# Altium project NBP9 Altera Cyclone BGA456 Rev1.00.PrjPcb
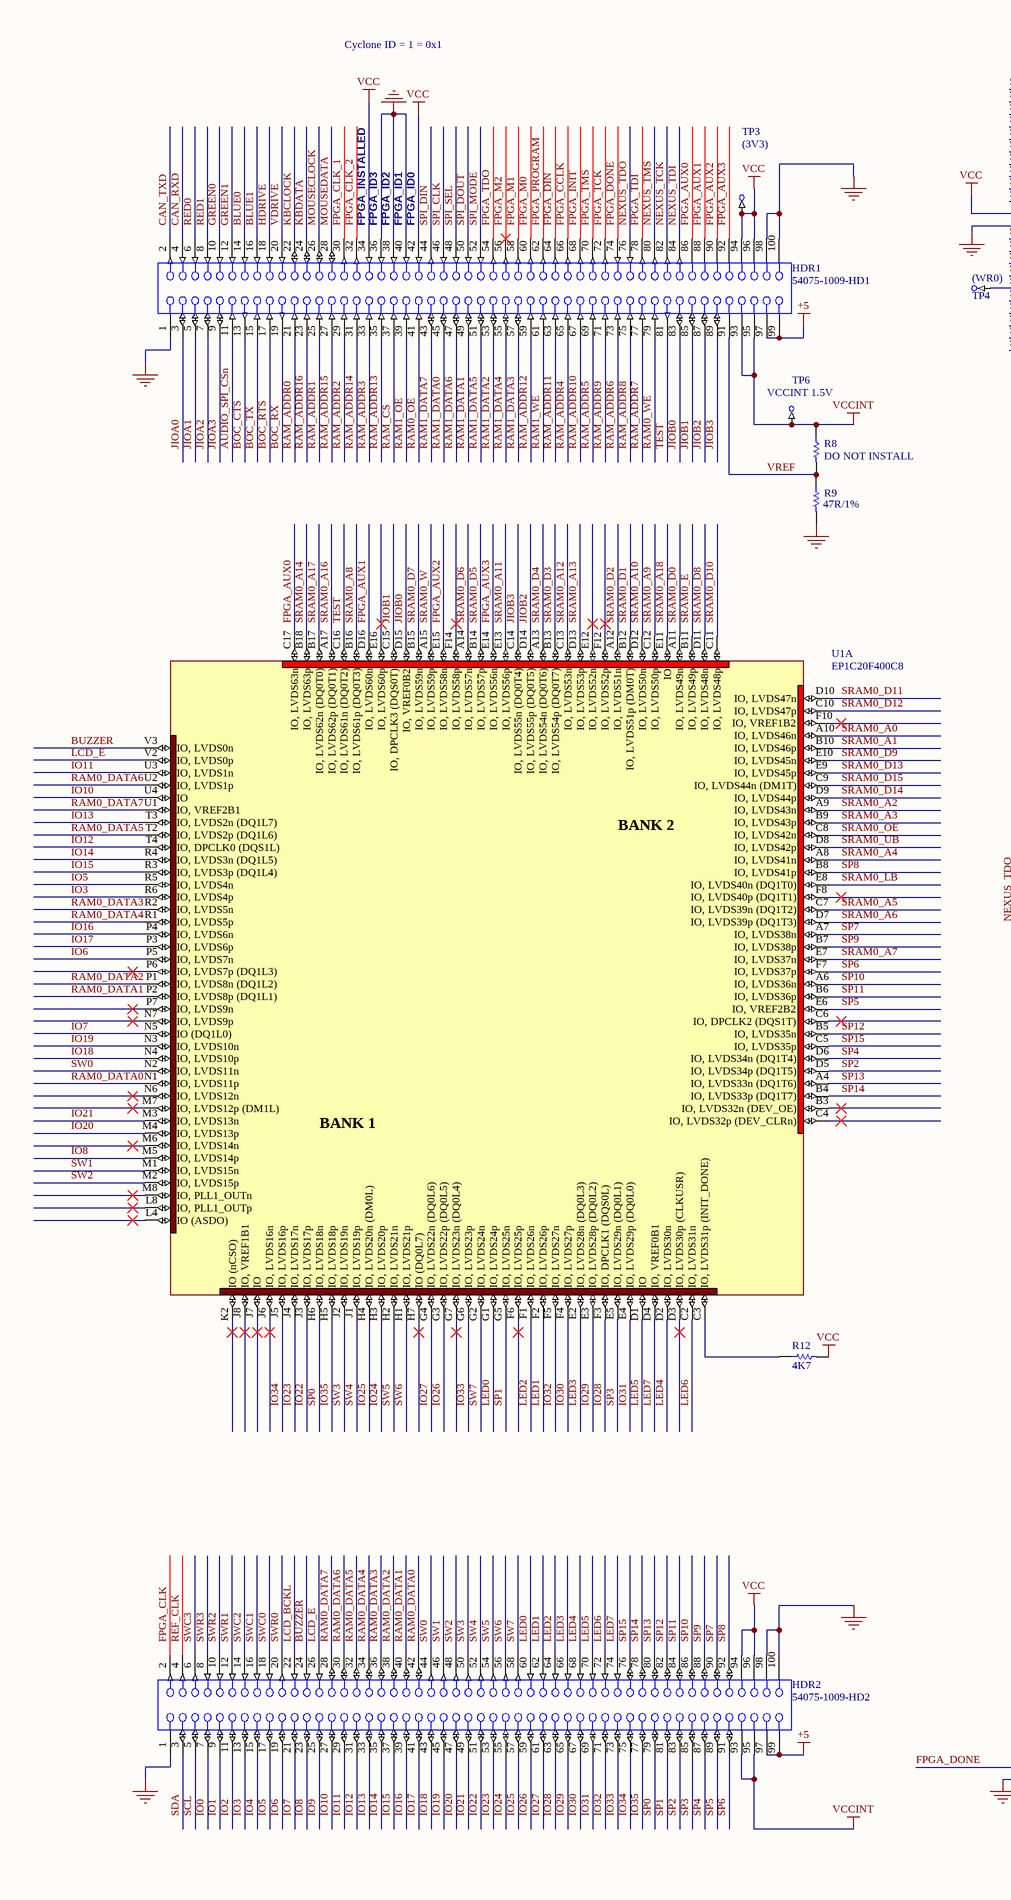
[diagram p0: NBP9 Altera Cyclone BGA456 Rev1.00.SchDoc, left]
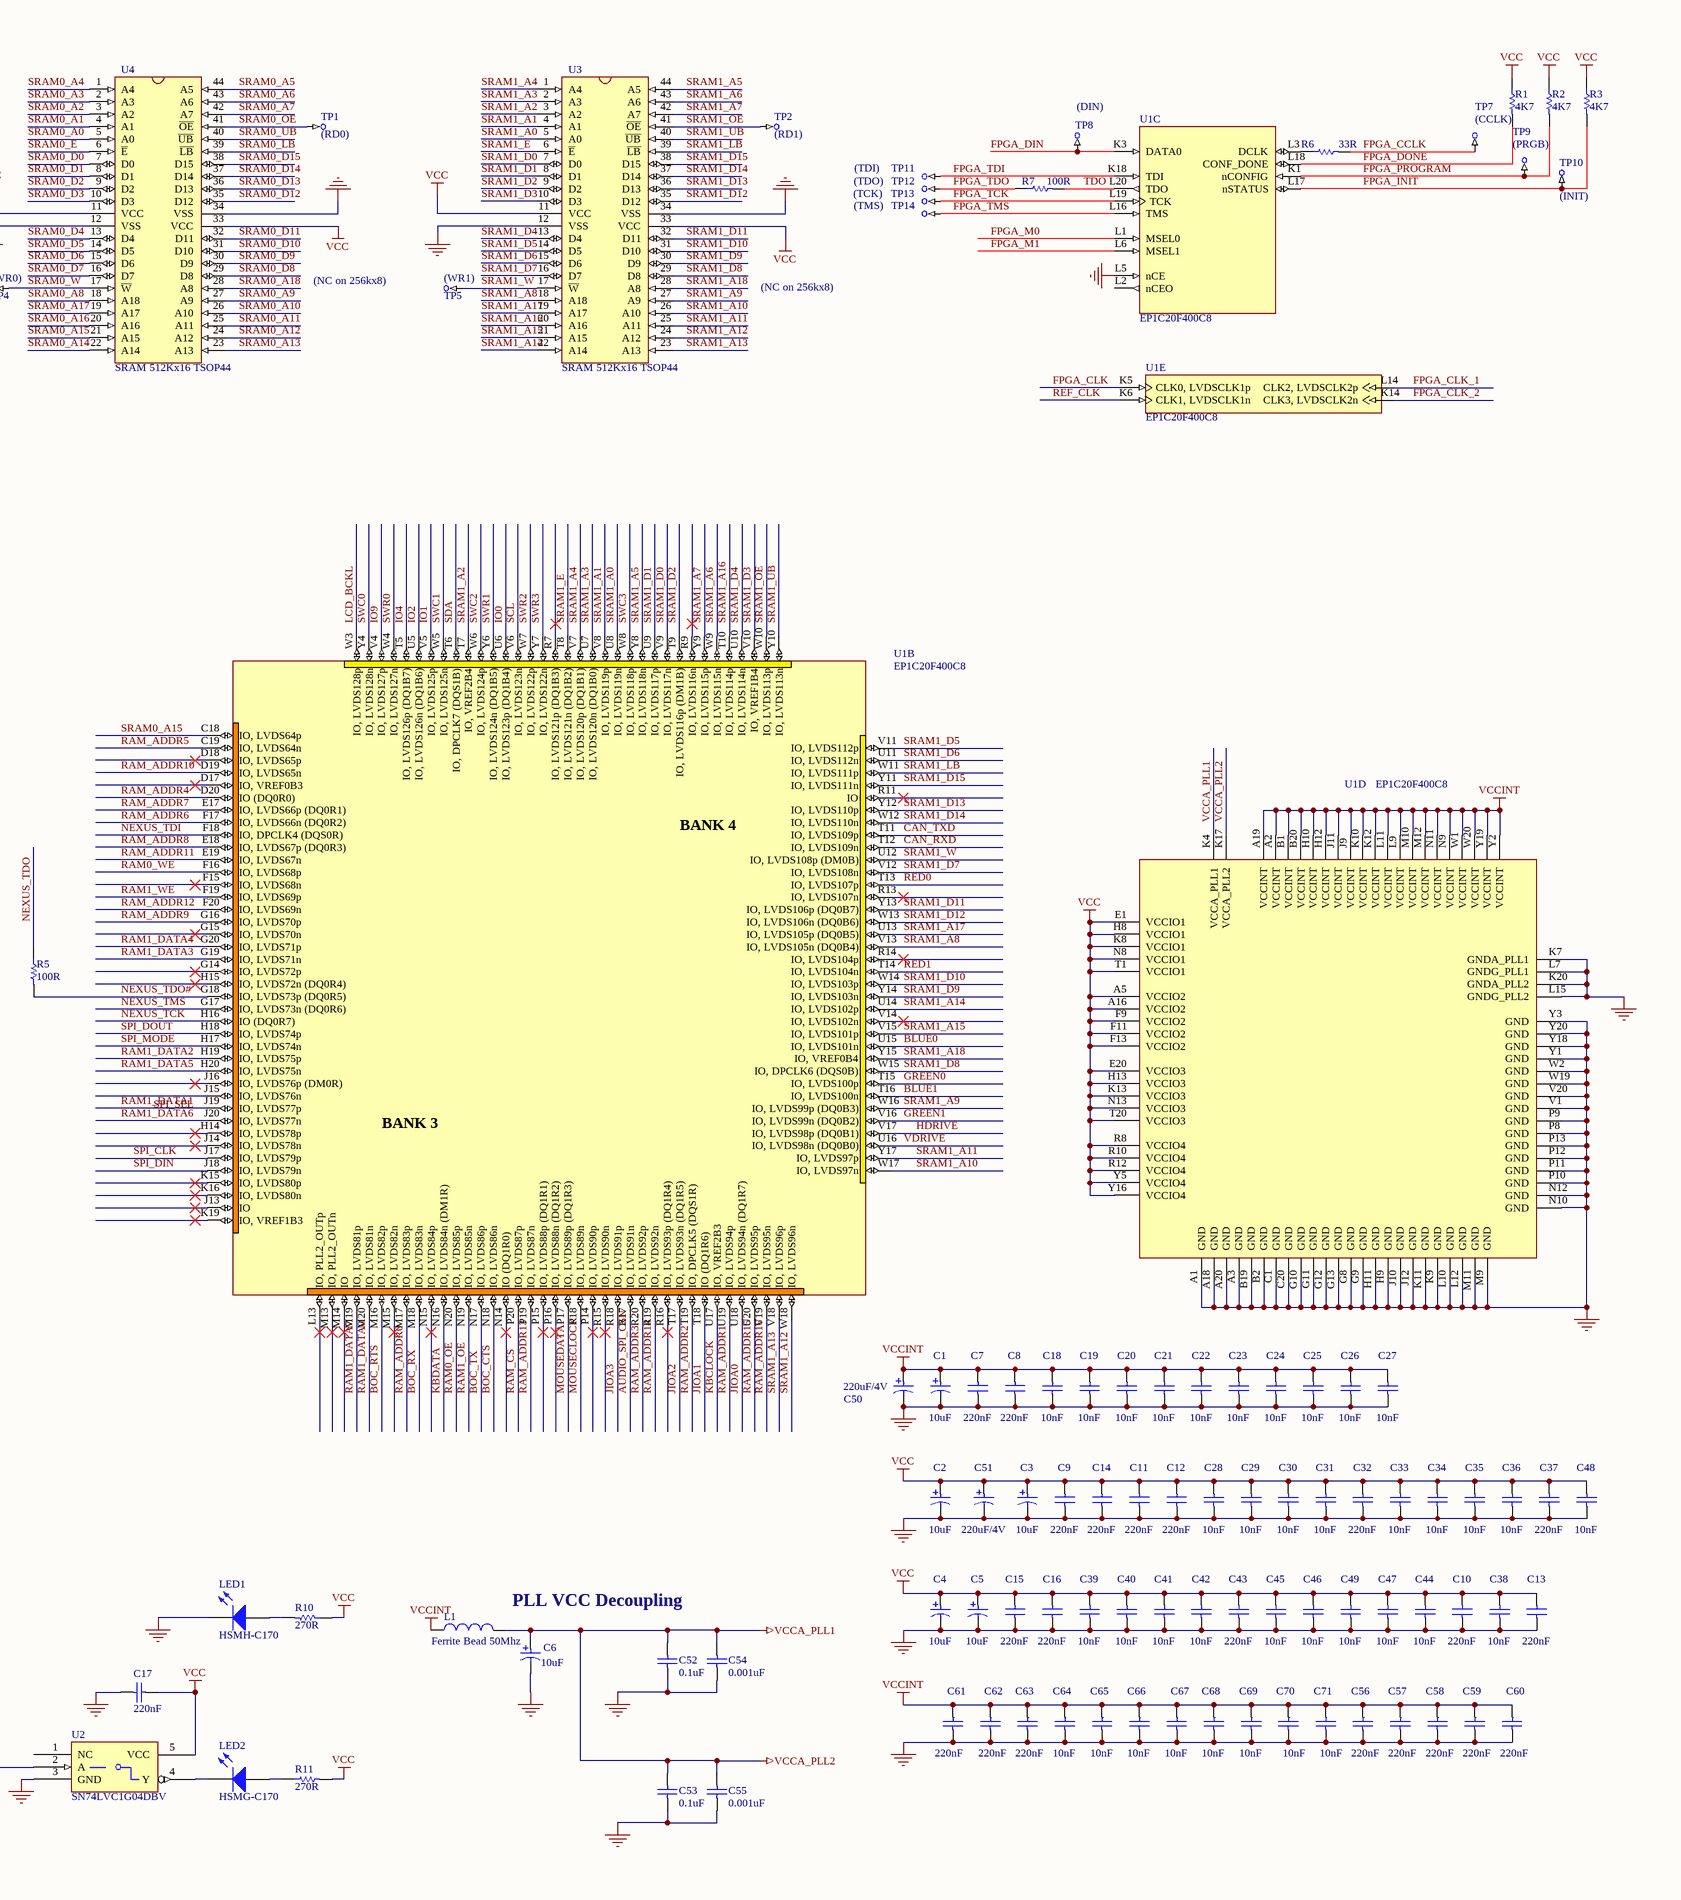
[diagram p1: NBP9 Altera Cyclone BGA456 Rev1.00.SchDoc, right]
1 sheet, 105 parts. Net scope: global (net labels, ports and power ports of the same name join across sheets).
Board file: NBP9 Altera Cyclone BGA456 Rev1.00.PcbDoc

## Sheet NBP9 Altera Cyclone BGA456 Rev1.00.SchDoc: Cyclone BGA400 Daughterboard
size A2; Author: Ch.W.; Organization: Altium Limited; Address1: L3, 12a Rodborough Rd; Address2: Frenchs Forest; Address3: NSW; Address4: Australia 2086; DocumentNumber: 1; Revision: 1.00; SheetNumber: 1; SheetTotal: 1

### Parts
C1  10uF  [MCCT-B]
C2  10uF  [MCCT-B]
C3  10uF  [MCCT-B]
C4  10uF  [MCCT-B]
C5  10uF  [MCCT-B]
C6  10uF  [MCCT-B]
C7  220nF  [CC1005-0402]
C8  220nF  [CC1005-0402]
C9  220nF  [CC1608-0603]
C10  220nF  [CC1005-0402]
C11  220nF  [CC1608-0603]
C12  220nF  [CC1608-0603]
C13  220nF  [CC1005-0402]
C14  220nF  [CC1608-0603]
C15  220nF  [CC1608-0603]
C16  220nF  [CC1608-0603]
C17  220nF  [CC1608-0603]
C18  10nF  [CC1005-0402]
C19  10nF  [CC1005-0402]
C20  10nF  [CC1005-0402]
C21  10nF  [CC1005-0402]
C22  10nF  [CC1005-0402]
C23  10nF  [CC1005-0402]
C24  10nF  [CC1005-0402]
C25  10nF  [CC1005-0402]
C26  10nF  [CC1005-0402]
C27  10nF  [CC1005-0402]
C28  10nF  [CC1608-0603]
C29  10nF  [CC1608-0603]
C30  10nF  [CC1005-0402]
C31  10nF  [CC1005-0402]
C32  220nF  [CC1608-0603]
C33  10nF  [CC1608-0603]
C34  10nF  [CC1608-0603]
C35  10nF  [CC1608-0603]
C36  10nF  [CC1005-0402]
C37  220nF  [CC1608-0603]
C38  10nF  [CC1005-0402]
C39  10nF  [CC1608-0603]
C40  10nF  [CC1608-0603]
C41  10nF  [CC1608-0603]
C42  10nF  [CC1608-0603]
C43  220nF  [CC1608-0603]
C44  10nF  [CC1005-0402]
C45  10nF  [CC1608-0603]
C46  10nF  [CC1608-0603]
C47  10nF  [CC1005-0402]
C48  10nF  [CC1608-0603]
C49  10nF  [CC1005-0402]
C50  220uF/4V  [MCCT-D]
C51  220uF/4V  [MCCT-D]
C52  0.1uF  [CC1608-0603]
C53  0.1uF  [CC1608-0603]
C54  0.001uF  [CC1005-0402]
C55  0.001uF  [CC1005-0402]
C56  220nF  [CC1608-0603]
C57  220nF  [CC1608-0603]
C58  220nF  [CC1608-0603]
C59  220nF  [CC1608-0603]
C60  220nF  [CC1608-0603]
C61  220nF  [CC1608-0603]
C62  220nF  [CC1608-0603]
C63  220nF  [CC1608-0603]
C64  10nF  [CC1608-0603]
C65  10nF  [CC1608-0603]
C66  10nF  [CC1608-0603]
C67  10nF  [CC1608-0603]
C68  10nF  [CC1608-0603]
C69  10nF  [CC1608-0603]
C70  10nF  [CC1608-0603]
C71  10nF  [CC1608-0603]
HDR1  54075-1009-HD1  [54075]
HDR2  54075-1009-HD2  [54075]
L1  Ferrite Bead 50Mhz  [CC1608-0603]
LED1  HSMH-C170  [SMD _LED]
LED2  HSMG-C170  [SMD _LED]
R1  4K7  [CC2012-0805]
R2  4K7  [CC2012-0805]
R3  4K7  [CC2012-0805]
R5  100R  [CR2012-0805]
R6  33R  [CC2012-0805]
R7  100R  [CC2012-0805]
R8  DO NOT INSTALL  [CR2012-0805]
R9  47R/1%  [CR2012-0805]
R10  270R  [CR2012-0805]
R11  270R  [CR2012-0805]
R12  4K7  [CC2012-0805]
TP1  (RD0)  [TestPin]  (no BOM)
TP2  (RD1)  [TestPin]  (no BOM)
TP3  (3V3)  [TestPin]  (no BOM)
TP4  (WR0)  [TestPin]  (no BOM)
TP5  (WR1)  [TestPin]  (no BOM)
TP6  VCCINT 1.5V  [TestPin]  (no BOM)
TP7  (CCLK)  [TestPin]  (no BOM)
TP8  (DIN)  [TestPin]  (no BOM)
TP9  (PRGB)  [TestPin]  (no BOM)
TP10  (INIT)  [TestPin]  (no BOM)
TP11  (TDI)  [TestPin]  (no BOM)
TP12  (TDO)  [TestPin]  (no BOM)
TP13  (TCK)  [TestPin]  (no BOM)
TP14  (TMS)  [TestPin]  (no BOM)
U1  EP1C20F400C8  [FBGA400]  (parts A,B,C,D,E of 5)
U2  SN74LVC1G04DBV  [SO-G5/P.95]
U3  SRAM 512Kx16 TSOP44  [SO-G44/P.8]
U4  SRAM 512Kx16 TSOP44  [SO-G44/P.8]

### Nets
+5: HDR1.97 HDR1.99 HDR2.97 HDR2.99
GND: C1.2 C2.2 C3.2 C4.2 C5.2 C6.2 C7.2 C8.2 C9.2 C10.2 C11.2 C12.2 C13.2 C14.2 C15.2 C16.2 C17.1 C18.2 C19.2 C20.2 C21.2 C22.2 C23.2 C24.2 C25.2 C26.2 C27.2 C28.2 C29.2 C30.2 C31.2 C32.2 C33.2 C34.2 C35.2 C36.2 C37.2 C38.2 C39.2 C40.2 C41.2 C42.2 C43.2 C44.2 C45.2 C46.2 C47.2 C48.2 C49.2 C50.2 C51.2 C52.2 C53.2 C54.2 C55.2 C56.2 C57.2 C58.2 C59.2 C60.2 C61.2 C62.2 C63.2 C64.2 C65.2 C66.2 C67.2 C68.2 C69.2 C70.2 C71.2 HDR1.1 HDR1.36 HDR1.38 HDR1.40 HDR1.98 HDR1.100 HDR2.1 HDR2.98 HDR2.100 LED1.2(K) R9.2 U1.A1(GND) U1.A3(GND) U1.A18(GND) U1.A20(GND) U1.B2(GND) U1.B19(GND) U1.C1(GND) U1.C20(GND) U1.G8(GND) U1.G9(GND) U1.G10(GND) U1.G11(GND) U1.G12(GND) U1.G13(GND) U1.H9(GND) U1.H11(GND) U1.J10(GND) U1.J12(GND) U1.K7(GNDA_PLL1) U1.K9(GND) U1.K11(GND) U1.K20(GNDA_PLL2) U1.L5(nCE) U1.L7(GNDG_PLL1) U1.L10(GND) U1.L12(GND) U1.L15(GNDG_PLL2) U1.M9(GND) U1.M11(GND) U1.N10(GND) U1.N12(GND) U1.P8(GND) U1.P9(GND) U1.P10(GND) U1.P11(GND) U1.P12(GND) U1.P13(GND) U1.V1(GND) U1.V20(GND) U1.W2(GND) U1.W19(GND) U1.Y1(GND) U1.Y3(GND) U1.Y18(GND) U1.Y20(GND) U2.3(GND) U3.12(VSS) U3.34(VSS) U4.12(VSS) U4.34(VSS)
VCC: C2.1 C3.1 C4.1 C5.1 C9.1 C10.1 C11.1 C12.1 C13.1 C14.1 C15.1 C16.1 C17.2 C28.1 C29.1 C30.1 C31.1 C32.1 C33.1 C34.1 C35.1 C36.1 C37.1 C38.1 C39.1 C40.1 C41.1 C42.1 C43.1 C44.1 C45.1 C46.1 C47.1 C48.1 C49.1 C51.1 HDR1.34 HDR1.42 HDR1.94 HDR1.96 HDR2.94 HDR2.96 R1.1 R2.1 R3.1 R10.1 R11.2 R12.2 TP3.1 U1.A5(VCCIO2) U1.A16(VCCIO2) U1.E1(VCCIO1) U1.E20(VCCIO3) U1.F9(VCCIO2) U1.F11(VCCIO2) U1.F13(VCCIO2) U1.H8(VCCIO1) U1.H13(VCCIO3) U1.K8(VCCIO1) U1.K13(VCCIO3) U1.N8(VCCIO1) U1.N13(VCCIO3) U1.R8(VCCIO4) U1.R10(VCCIO4) U1.R12(VCCIO4) U1.T1(VCCIO1) U1.T20(VCCIO3) U1.Y5(VCCIO4) U1.Y16(VCCIO4) U2.5(VCC) U3.11(VCC) U3.33(VCC) U4.11(VCC) U4.33(VCC)
VCCA_PLL1: C6.1 C52.1 C53.1 C54.1 C55.1 L1.2 U1.K4(VCCA_PLL1) U1.K17(VCCA_PLL2)  [also labelled VCCA_PLL2]
VCCINT: C1.1 C7.1 C8.1 C18.1 C19.1 C20.1 C21.1 C22.1 C23.1 C24.1 C25.1 C26.1 C27.1 C50.1 C56.1 C57.1 C58.1 C59.1 C60.1 C61.1 C62.1 C63.1 C64.1 C65.1 C66.1 C67.1 C68.1 C69.1 C70.1 C71.1 HDR1.93 HDR1.95 HDR2.93 HDR2.95 L1.1 R8.1 TP6.1 U1.A2(VCCINT) U1.A19(VCCINT) U1.B1(VCCINT) U1.B20(VCCINT) U1.H10(VCCINT) U1.H12(VCCINT) U1.J9(VCCINT) U1.J11(VCCINT) U1.K10(VCCINT) U1.K12(VCCINT) U1.L9(VCCINT) U1.L11(VCCINT) U1.M10(VCCINT) U1.M12(VCCINT) U1.N9(VCCINT) U1.N11(VCCINT) U1.W1(VCCINT) U1.W20(VCCINT) U1.Y2(VCCINT) U1.Y19(VCCINT)
AUDIO_SPI_CSn: HDR1.11 U1.R17(IO,_LVDS91n)
BLUE0: HDR1.14 U1.U15(IO,_LVDS101n)
BLUE1: HDR1.16 U1.T16(IO,_LVDS100n)
BOC_CTS: HDR1.13 U1.N18(IO,_LVDS86n)
BOC_RTS: HDR1.17 U1.M16(IO,_LVDS82p)
BOC_RX: HDR1.19 U1.M18(IO,_LVDS83n)
BOC_TX: HDR1.15 U1.N17(IO,_LVDS86p)
BUZZER: HDR2.24 U1.V3(IO,_LVDS0n)
CAN_RXD: HDR1.4 U1.T12(IO,_LVDS109n)
CAN_TXD: HDR1.2 U1.T11(IO,_LVDS109p)
FPGA_AUX0: HDR1.86 U1.C17(IO,_LVDS63n)
FPGA_AUX1: HDR1.88 U1.D16(IO,_LVDS60n)
FPGA_AUX2: HDR1.90 U1.E15(IO,_LVDS58n)
FPGA_AUX3: HDR1.92 U1.E14(IO,_LVDS56n)
FPGA_CCLK: HDR1.66 R6.2 TP7.1
FPGA_CLK: HDR2.2 U1.K5(CLK0,_LVDSCLK1p)
FPGA_CLK_1: HDR1.30 U1.L14(CLK2,_LVDSCLK2p)
FPGA_CLK_2: HDR1.32 U1.K14(CLK3,_LVDSCLK2n)
FPGA_DIN: HDR1.64 TP8.1 U1.K3(DATA0)
FPGA_DONE: HDR1.74 R1.2 U1.L18(CONF_DONE) U2.2(A)
FPGA_INIT: HDR1.68 R3.2 TP10.1 U1.L17(nSTATUS)
FPGA_M0: HDR1.60 U1.L1(MSEL0)
FPGA_M1: HDR1.58 U1.L6(MSEL1)
FPGA_M2: HDR1.56
FPGA_PROGRAM: HDR1.62 R2.2 TP9.1 U1.K1(nCONFIG)
FPGA_TCK: HDR1.72 TP13.1 U1.L19(TCK)
FPGA_TDI: HDR1.78 TP11.1 U1.K18(TDI)
FPGA_TDO: HDR1.54 R7.1 TP12.1
FPGA_TMS: HDR1.70 TP14.1 U1.L16(TMS)
GREEN0: HDR1.10 U1.T15(IO,_LVDS100p)
GREEN1: HDR1.12 U1.V16(IO,_LVDS99n_(DQ0B2))
HDRIVE: HDR1.18 U1.V17(IO,_LVDS98p_(DQ0B1))
IO0: HDR2.7 U1.U6(IO,_LVDS123p_(DQ1B4))
IO1: HDR2.9 U1.V5(IO,_LVDS125p)
IO2: HDR2.11 U1.U5(IO,_LVDS126n_(DQ1B6))
IO3: HDR2.13 U1.R6(IO,_LVDS4p)
IO4: HDR2.15 U1.T5(IO,_LVDS126p_(DQ1B7))
IO5: HDR2.17 U1.R5(IO,_LVDS4n)
IO6: HDR2.19 U1.P5(IO,_LVDS7n)
IO7: HDR2.21 U1.N5(IO_(DQ1L0))
IO8: HDR2.23 U1.M5(IO,_LVDS14p)
IO9: HDR2.25 U1.V4(IO,_LVDS127p)
IO10: HDR2.27 U1.U4(IO)
IO11: HDR2.29 U1.U3(IO,_LVDS1n)
IO12: HDR2.31 U1.T4(IO,_DPCLK0_(DQS1L))
IO13: HDR2.33 U1.T3(IO,_LVDS2n_(DQ1L7))
IO14: HDR2.35 U1.R4(IO,_LVDS3n_(DQ1L5))
IO15: HDR2.37 U1.R3(IO,_LVDS3p_(DQ1L4))
IO16: HDR2.39 U1.P4(IO,_LVDS6n)
IO17: HDR2.41 U1.P3(IO,_LVDS6p)
IO18: HDR2.43 U1.N4(IO,_LVDS10p)
IO19: HDR2.45 U1.N3(IO,_LVDS10n)
IO20: HDR2.47 U1.M4(IO,_LVDS13p)
IO21: HDR2.49 U1.M3(IO,_LVDS13n)
IO22: HDR2.51 U1.J3(IO,_LVDS17p)
IO23: HDR2.53 U1.J4(IO,_LVDS17n)
IO24: HDR2.55 U1.H3(IO,_LVDS20p)
IO25: HDR2.57 U1.H4(IO,_LVDS20n_(DM0L))
IO26: HDR2.59 U1.G3(IO,_LVDS22p_(DQ0L5))
IO27: HDR2.61 U1.G4(IO,_LVDS22n_(DQ0L6))
IO28: HDR2.63 U1.F3(IO,_DPCLK1_(DQS0L))
IO29: HDR2.65 U1.E3(IO,_LVDS28p_(DQ0L2))
IO30: HDR2.67 U1.F4(IO,_LVDS27p)
IO31: HDR2.69 U1.E4(IO,_LVDS29p_(DQ0L0))
IO32: HDR2.71 U1.F5(IO,_LVDS27n)
IO33: HDR2.73 U1.G6(IO,_LVDS23p)
IO34: HDR2.75 U1.J5(IO,_LVDS16p)
IO35: HDR2.77 U1.H5(IO,_LVDS18p)
JIOA0: HDR1.3 U1.U18(IO,_LVDS94n_(DQ1R7))
JIOA1: HDR1.5 U1.T18(IO_(DQ1R6))
JIOA2: HDR1.7 U1.T17(IO,_LVDS93n_(DQ1R5))
JIOA3: HDR1.9 U1.R18(IO,_LVDS91p)
JIOB0: HDR1.83 U1.D15(IO,_VREF0B2)
JIOB1: HDR1.85 U1.C15(IO,_DPCLK3_(DQS0T))
JIOB2: HDR1.87 U1.D14(IO,_LVDS55p_(DQ0T5))
JIOB3: HDR1.89 U1.C14(IO,_LVDS55n_(DQ0T4))
KBCLOCK: HDR1.22 U1.U17(IO,_VREF2B3)
KBDATA: HDR1.24 U1.N16(IO,_LVDS84n_(DM1R))
LCD_BCKL: HDR2.22 U1.W3(IO,_LVDS128p)
LCD_E: HDR2.26 U1.V2(IO,_LVDS0p)
LED0: HDR2.60 U1.G1(IO,_LVDS24p)
LED1: HDR2.62 U1.F2(IO,_LVDS26p)
LED2: HDR2.64 U1.F1(IO,_LVDS26n)
LED3: HDR2.66 U1.E2(IO,_LVDS28n_(DQ0L3))
LED4: HDR2.68 U1.D2(IO,_LVDS30n)
LED5: HDR2.70 U1.D1(IO)
LED6: HDR2.72 U1.C2(IO,_LVDS31n)
LED7: HDR2.74 U1.D4(IO,_VREF0B1)
MOUSECLOCK: HDR1.26 U1.P18(IO,_LVDS89n)
MOUSEDATA: HDR1.28 U1.P17(IO,_LVDS89p_(DQ1R3))
NEXUS_TCK: HDR1.82 U1.H16(IO_(DQ0R7))
NEXUS_TDI: HDR1.84 U1.F18(IO,_DPCLK4_(DQS0R))
NEXUS_TDO: HDR1.76 R5.1
NEXUS_TDO#: R5.2 U1.G18(IO,_LVDS73p_(DQ0R5))
NEXUS_TMS: HDR1.80 U1.G17(IO,_LVDS73n_(DQ0R6))
RAM0_DATA0: HDR2.42 U1.N1(IO,_LVDS11p)
RAM0_DATA1: HDR2.40 U1.P2(IO,_LVDS8p_(DQ1L1))
RAM0_DATA2: HDR2.38 U1.P1(IO,_LVDS8n_(DQ1L2))
RAM0_DATA3: HDR2.36 U1.R2(IO,_LVDS5n)
RAM0_DATA4: HDR2.34 U1.R1(IO,_LVDS5p)
RAM0_DATA5: HDR2.32 U1.T2(IO,_LVDS2p_(DQ1L6))
RAM0_DATA6: HDR2.30 U1.U2(IO,_LVDS1p)
RAM0_DATA7: HDR2.28 U1.U1(IO,_VREF2B1)
RAM0_OE: HDR1.41 U1.N20(IO,_LVDS85p)
RAM0_WE: HDR1.79 U1.F16(IO,_LVDS68p)
RAM1_DATA0: HDR1.45 U1.M20(IO,_LVDS81n)
RAM1_DATA1: HDR1.49 U1.J19(IO,_LVDS77p)
RAM1_DATA2: HDR1.53 U1.H19(IO,_LVDS75p)
RAM1_DATA3: HDR1.57 U1.G19(IO,_LVDS71n)
RAM1_DATA4: HDR1.55 U1.G20(IO,_LVDS71p)
RAM1_DATA5: HDR1.51 U1.H20(IO,_LVDS75n)
RAM1_DATA6: HDR1.47 U1.J20(IO,_LVDS77n)
RAM1_DATA7: HDR1.43 U1.M19(IO,_LVDS81p)
RAM1_OE: HDR1.39 U1.N19(IO,_LVDS85n)
RAM1_WE: HDR1.61 U1.F19(IO,_LVDS69p)
RAM_ADDR0: HDR1.21 U1.M17(IO,_LVDS83p)
RAM_ADDR1: HDR1.25 U1.U19(IO,_LVDS94p)
RAM_ADDR2: HDR1.29 U1.T19(IO,_DPCLK5_(DQS1R))
RAM_ADDR3: HDR1.33 U1.R20(IO,_LVDS92p)
RAM_ADDR4: HDR1.65 U1.D20(IO_(DQ0R0))
RAM_ADDR5: HDR1.69 U1.C19(IO,_LVDS64n)
RAM_ADDR6: HDR1.73 U1.F17(IO,_LVDS66n_(DQ0R2))
RAM_ADDR7: HDR1.77 U1.E17(IO,_LVDS66p_(DQ0R1))
RAM_ADDR8: HDR1.75 U1.E18(IO,_LVDS67p_(DQ0R3))
RAM_ADDR9: HDR1.71 U1.G16(IO,_LVDS70p)
RAM_ADDR10: HDR1.67 U1.D19(IO,_LVDS65n)
RAM_ADDR11: HDR1.63 U1.E19(IO,_LVDS67n)
RAM_ADDR12: HDR1.59 U1.F20(IO,_LVDS69n)
RAM_ADDR13: HDR1.35 U1.P19(IO,_LVDS87n)
RAM_ADDR14: HDR1.31 U1.R19(IO,_LVDS92n)
RAM_ADDR15: HDR1.27 U1.U20(IO,_LVDS95p)
RAM_ADDR16: HDR1.23 U1.V19(IO,_LVDS95n)
RAM_CS: HDR1.37 U1.P20(IO,_LVDS87p)
RED0: HDR1.6 U1.T13(IO,_LVDS107p)
RED1: HDR1.8 U1.T14(IO,_LVDS104n)
REF_CLK: HDR2.4 U1.K6(CLK1,_LVDSCLK1n)
SCL: HDR2.5 U1.V6(IO,_LVDS123n)
SDA: HDR2.3 U1.T6(IO,_DPCLK7_(DQS1B))
SP0: HDR2.79 U1.H6(IO,_LVDS18n)
SP1: HDR2.81 U1.G5(IO,_LVDS25n)
SP2: HDR2.83 U1.D5(IO,_LVDS34p_(DQ1T5))
SP3: HDR2.85 U1.E5(IO,_LVDS29n_(DQ0L1))
SP4: HDR2.87 U1.D6(IO,_LVDS34n_(DQ1T4))
SP5: HDR2.89 U1.E6(IO,_VREF2B2)
SP6: HDR2.91 U1.F7(IO,_LVDS37p)
SP7: HDR2.90 U1.A7(IO,_LVDS38n)
SP8: HDR2.92 U1.B8(IO,_LVDS41p)
SP9: HDR2.88 U1.B7(IO,_LVDS38p)
SP10: HDR2.86 U1.A6(IO,_LVDS36n)
SP11: HDR2.84 U1.B6(IO,_LVDS36p)
SP12: HDR2.82 U1.B5(IO,_LVDS35n)
SP13: HDR2.80 U1.A4(IO,_LVDS33n_(DQ1T6))
SP14: HDR2.78 U1.B4(IO,_LVDS33p_(DQ1T7))
SP15: HDR2.76 U1.C5(IO,_LVDS35p)
SPI_CLK: HDR1.46 U1.J17(IO,_LVDS79p)
SPI_DIN: HDR1.44 U1.J18(IO,_LVDS79n)
SPI_DOUT: HDR1.50 U1.H18(IO,_LVDS74p)
SPI_MODE: HDR1.52 U1.H17(IO,_LVDS74n)
SPI_SEL: HDR1.48 U1.J15(IO,_LVDS76n)
SRAM0_A0: U1.A10(IO,_LVDS46n) U3.5(A0)
SRAM0_A1: U1.B10(IO,_LVDS46p) U3.4(A1)
SRAM0_A2: U1.A9(IO,_LVDS43n) U3.3(A2)
SRAM0_A3: U1.B9(IO,_LVDS43p) U3.2(A3)
SRAM0_A4: U1.A8(IO,_LVDS41n) U3.1(A4)
SRAM0_A5: U1.C7(IO,_LVDS39n_(DQ1T2)) U3.44(A5)
SRAM0_A6: U1.D7(IO,_LVDS39p_(DQ1T3)) U3.43(A6)
SRAM0_A7: U1.E7(IO,_LVDS37n) U3.42(A7)
SRAM0_A8: U1.B16(IO,_LVDS61p_(DQ0T3)) U3.18(A18)
SRAM0_A9: U1.C12(IO,_LVDS50p) U3.27(A9)
SRAM0_A10: U1.D12(IO,_LVDS50n) U3.26(A10)
SRAM0_A11: U1.E13(IO,_LVDS56p) U3.25(A11)
SRAM0_A12: U1.C13(IO,_LVDS53n) U3.24(A12)
SRAM0_A13: U1.D13(IO,_LVDS53p) U3.23(A13)
SRAM0_A14: U1.B18(IO,_LVDS63p) U3.22(A14)
SRAM0_A15: U1.C18(IO,_LVDS64p) U3.21(A15)
SRAM0_A16: U1.A17(IO,_LVDS62p_(DQ0T1)) U3.20(A16)
SRAM0_A17: U1.B17(IO,_LVDS62n_(DQ0T0)) U3.19(A17)
SRAM0_A18: U1.E11(IO) U3.28(A8)
SRAM0_D0: U1.A11(IO,_LVDS49n) U3.7(D0)
SRAM0_D1: U1.B12(IO,_LVDS51p_(DM0T)) U3.8(D1)
SRAM0_D2: U1.A12(IO,_LVDS51n) U3.9(D2)
SRAM0_D3: U1.B13(IO,_LVDS54p_(DQ0T7)) U3.10(D3)
SRAM0_D4: U1.A13(IO,_LVDS54n_(DQ0T6)) U3.13(D4)
SRAM0_D5: U1.B14(IO,_LVDS57p) U3.14(D5)
SRAM0_D6: U1.A14(IO,_LVDS57n) U3.15(D6)
SRAM0_D7: U1.B15(IO,_LVDS59n) U3.16(D7)
SRAM0_D8: U1.D11(IO,_LVDS48n) U3.29(D8)
SRAM0_D9: U1.E10(IO,_LVDS45n) U3.30(D9)
SRAM0_D10: U1.C11(IO,_LVDS48p) U3.31(D10)
SRAM0_D11: U1.D10(IO,_LVDS47n) U3.32(D11)
SRAM0_D12: U1.C10(IO,_LVDS47p) U3.35(D12)
SRAM0_D13: U1.E9(IO,_LVDS45p) U3.36(D13)
SRAM0_D14: U1.D9(IO,_LVDS44p) U3.37(D14)
SRAM0_D15: U1.C9(IO,_LVDS44n_(DM1T)) U3.38(D15)
SRAM0_E: U1.B11(IO,_LVDS49p) U3.6(~{E})
SRAM0_LB: U1.E8(IO,_LVDS40n_(DQ1T0)) U3.39(~{LB})
SRAM0_OE: TP1.1 U1.C8(IO,_LVDS42n) U3.41(~{OE})
SRAM0_UB: U1.D8(IO,_LVDS42p) U3.40(~{UB})
SRAM0_W: TP4.1 U1.A15(IO,_LVDS59p) U3.17(~{W})
SRAM1_A0: U1.U8(IO,_LVDS119n) U4.5(A0)
SRAM1_A1: U1.V8(IO,_LVDS119p) U4.4(A1)
SRAM1_A2: U1.T7(IO,_VREF2B4) U4.3(A2)
SRAM1_A3: U1.U7(IO,_LVDS120n_(DQ1B0)) U4.2(A3)
SRAM1_A4: U1.V7(IO,_LVDS120p_(DQ1B1)) U4.1(A4)
SRAM1_A5: U1.Y8(IO,_LVDS118n) U4.44(A5)
SRAM1_A6: U1.W9(IO,_LVDS115n) U4.43(A6)
SRAM1_A7: U1.Y9(IO,_LVDS115p) U4.42(A7)
SRAM1_A8: U1.V13(IO,_LVDS105n_(DQ0B4)) U4.18(A18)
SRAM1_A9: U1.W16(IO,_LVDS99p_(DQ0B3)) U4.27(A9)
SRAM1_A10: U1.W17(IO,_LVDS97n) U4.26(A10)
SRAM1_A11: U1.Y17(IO,_LVDS97p) U4.25(A11)
SRAM1_A12: U1.W18(IO,_LVDS96n) U4.24(A12)
SRAM1_A13: U1.V18(IO,_LVDS96p) U4.23(A13)
SRAM1_A14: U1.U14(IO,_LVDS102p) U4.22(A14)
SRAM1_A15: U1.V15(IO,_LVDS101p) U4.21(A15)
SRAM1_A16: U1.T10(IO,_LVDS114p) U4.20(A16)
SRAM1_A17: U1.U13(IO,_LVDS105p_(DQ0B5)) U4.19(A17)
SRAM1_A18: U1.Y15(IO,_VREF0B4) U4.28(A8)
SRAM1_D0: U1.V9(IO,_LVDS117n) U4.7(D0)
SRAM1_D1: U1.U9(IO,_LVDS117p) U4.8(D1)
SRAM1_D2: U1.T9(IO,_LVDS116p_(DM1B)) U4.9(D2)
SRAM1_D3: U1.V10(IO,_VREF1B4) U4.10(D3)
SRAM1_D4: U1.U10(IO,_LVDS114n) U4.13(D4)
SRAM1_D5: U1.V11(IO,_LVDS112p) U4.14(D5)
SRAM1_D6: U1.U11(IO,_LVDS112n) U4.15(D6)
SRAM1_D7: U1.V12(IO,_LVDS108n) U4.16(D7)
SRAM1_D8: U1.W15(IO,_DPCLK6_(DQS0B)) U4.29(D8)
SRAM1_D9: U1.Y14(IO,_LVDS103n) U4.30(D9)
SRAM1_D10: U1.W14(IO,_LVDS103p) U4.31(D10)
SRAM1_D11: U1.Y13(IO,_LVDS106p_(DQ0B7)) U4.32(D11)
SRAM1_D12: U1.W13(IO,_LVDS106n_(DQ0B6)) U4.35(D12)
SRAM1_D13: U1.Y12(IO,_LVDS110p) U4.36(D13)
SRAM1_D14: U1.W12(IO,_LVDS110n) U4.37(D14)
SRAM1_D15: U1.Y11(IO,_LVDS111n) U4.38(D15)
SRAM1_E: U1.T8(IO,_LVDS121n_(DQ1B2)) U4.6(~{E})
SRAM1_LB: U1.W11(IO,_LVDS111p) U4.39(~{LB})
SRAM1_OE: TP2.1 U1.W10(IO,_LVDS113p) U4.41(~{OE})
SRAM1_UB: U1.Y10(IO,_LVDS113n) U4.40(~{UB})
SRAM1_W: TP5.1 U1.U12(IO,_LVDS108p_(DM0B)) U4.17(~{W})
SW0: HDR2.44 U1.N2(IO,_LVDS11n)
SW1: HDR2.46 U1.M1(IO,_LVDS15n)
SW2: HDR2.48 U1.M2(IO,_LVDS15p)
SW3: HDR2.50 U1.J2(IO,_LVDS19n)
SW4: HDR2.52 U1.J1(IO,_LVDS19p)
SW5: HDR2.54 U1.H2(IO,_LVDS21n)
SW6: HDR2.56 U1.H1(IO,_LVDS21p)
SW7: HDR2.58 U1.G2(IO,_LVDS24n)
SWC0: HDR2.18 U1.Y4(IO,_LVDS128n)
SWC1: HDR2.16 U1.W5(IO,_LVDS125n)
SWC2: HDR2.14 U1.W6(IO,_LVDS124p)
SWC3: HDR2.6 U1.W8(IO,_LVDS118p)
SWR0: HDR2.20 U1.W4(IO,_LVDS127n)
SWR1: HDR2.12 U1.Y6(IO,_LVDS124n_(DQ1B5))
SWR2: HDR2.10 U1.W7(IO,_LVDS122p)
SWR3: HDR2.8 U1.Y7(IO,_LVDS122n)
TDO: R7.2 U1.L20(TDO)
TEST: HDR1.81 U1.C16(IO,_LVDS61n_(DQ0T2))
VDRIVE: HDR1.20 U1.U16(IO,_LVDS98n_(DQ0B0))
VREF: HDR1.91 R8.2 R9.1
NetLED1_1: LED1.1(A) R10.2
NetLED2_1: LED2.1(A) R11.1
NetLED2_2: LED2.2(K) U2.4(Y)
NetR6_1: R6.1 U1.L3(DCLK)
NetR12_1: R12.1 U1.C3(IO,_LVDS31p_(INIT_DONE))

Not connected (* = marked no-connect by the designer): U1 B3(IO,_LVDS32n_(DEV_OE))* C4(IO,_LVDS32p_(DEV_CLRn))* C6(IO,_DPCLK2_(DQS1T))* D3(IO,_LVDS30p_(CLKUSR))* D17(IO,_VREF0B3)* D18(IO,_LVDS65p)* E12(IO,_LVDS52n)* E16(IO,_LVDS60p)* F6(IO,_LVDS25p)* F8(IO,_LVDS40p_(DQ1T1))* F10(IO,_VREF1B2)* F12(IO,_LVDS52p)* F14(IO,_LVDS58p)* F15(IO,_LVDS68n)* G7(IO,_LVDS23n_(DQ0L4))* G14(IO,_LVDS72p)* G15(IO,_LVDS70n)* H7(IO_(DQ0L7))* H14(IO,_LVDS78p)* H15(IO,_LVDS72n_(DQ0R4))* J6(IO,_LVDS16n)* J7(IO)* J8(IO,_VREF1B1)* J13(IO)* J14(IO,_LVDS78n)* J16(IO,_LVDS76p_(DM0R))* K2(IO_(nCSO))* K15(IO,_LVDS80p)* K16(IO,_LVDS80n)* K19(IO,_VREF1B3)* L2(nCEO) L4(IO_(ASDO))* L8(IO,_PLL1_OUTp)* L13(IO,_PLL2_OUTp)* M6(IO,_LVDS14n)* M7(IO,_LVDS12p_(DM1L))* M8(IO,_PLL1_OUTn)* M13(IO,_PLL2_OUTn)* M14(IO)* M15(IO,_LVDS82n)* N6(IO,_LVDS12n)* N7(IO,_LVDS9p)* N14(IO_(DQ1R0))* N15(IO,_LVDS84p)* P6(IO,_LVDS7p_(DQ1L3))* P7(IO,_LVDS9n)* P14(IO,_LVDS90p)* P15(IO,_LVDS88p_(DQ1R1))* P16(IO,_LVDS88n_(DQ1R2))* R7(IO,_LVDS121p_(DQ1B3))* R9(IO,_LVDS116n)* R11(IO)* R13(IO,_LVDS107n)* R14(IO,_LVDS104p)* R15(IO,_LVDS90n)* R16(IO,_LVDS93p_(DQ1R4))* V14(IO,_LVDS102n)*; U2 1(NC)

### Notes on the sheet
- Cyclone ID = 1 = 0x1
- (near HDR1) FPGA_INSTALLED
- (near HDR1) FPGA_ID3
- (near HDR1) FPGA_ID2
- (near HDR1) FPGA_ID1
- (near HDR1) FPGA_ID0
- (NC on 256kx8)
- PLL VCC Decoupling

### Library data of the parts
C1-C6 C50 C51 = CAP_POLAR: Polar Capacitor
C7-C49 C52-C71 = CAP: Capacitor
HDR1 = 54075-1009-HD1: Board-to-Board, Docking Station, 0.80mm (.031") Pitch, Shielded Receptacle, Vertical, Ultra Low Profile, SMT; Manufacturer: Molex; Package Information: Latest Revision: Jun-2001; Mating Height: 8.5mm; Voltage: 100V; Current: 0.5A; Contact Resistance: 40mOhm max; PCB Layout: Complies with Manufacturer's Recommendation.
HDR2 = 54075-1009-HD2: Board-to-Board, Docking Station, 0.80mm (.031") Pitch, Shielded Receptacle, Vertical, Ultra Low Profile, SMT; Manufacturer: Molex; Package Information: Latest Revision: Jun-2001; Mating Height: 8.5mm; Voltage: 100V; Current: 0.5A; Contact Resistance: 40mOhm max; PCB Layout: Complies with Manufacturer's Recommendation.
L1 = Inductor: Ferrite Bead; Value: 10mH
LED1 LED2 = HSMX-C670: Typical RED GaAs SMD LED Agilent make; Manufacturer: Generic Components; Class I: Optoelectronic; Fitted: True
R1-R3 R5-R12 = RES: Resistor
TP1-TP14 = TestPin
U1 = EP1C20F400C8: Cyclone Family, 1.5V FPGA, 301 I/O Pins, 2 x PLLs, Commercial Grade, Speed Grade 8; PackageDocument: ver11.0, Feb-2003
U2 = SN74AHC1G04DBVR: Manufacturer: TI; Fitted: True
U3 U4 = SRAM 512Kx16 TSOP44: 512Kx16Bit SRAM TSOP44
